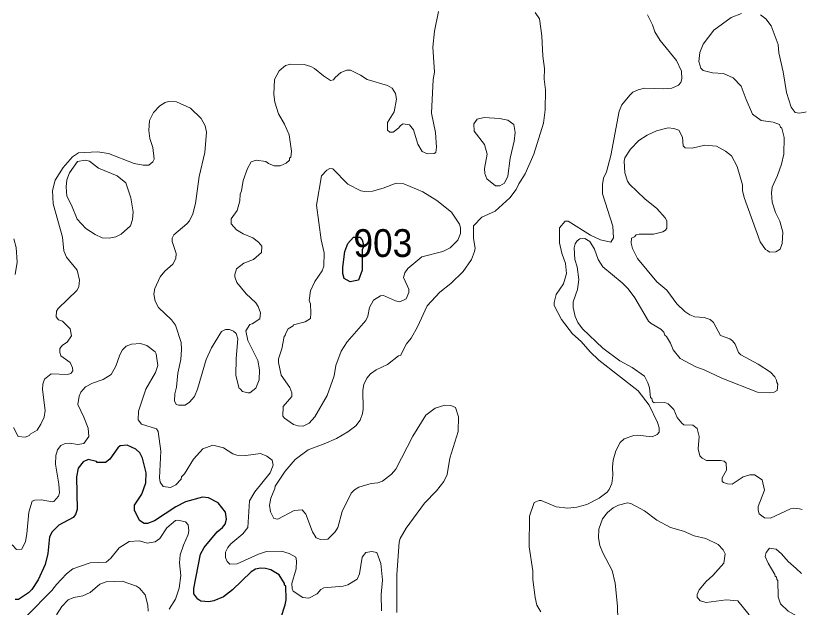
# Model space of a CAD drawing. Extents: x 598.3 to 623.2, y 6902.2 to 6930.1.
# Drawn here: x 620.795 to 623.07, y 6916.455 to 6918.158 of the extents above; entities that cross this region are included whole.
import ezdxf

# ---------------------------------------------------------------- set-up
doc = ezdxf.new("R2010")
doc.units = 0
doc.header["$LTSCALE"] = 0.032
doc.layers.add('1', color=7, linetype='Continuous', lineweight=25)
doc.layers.add('2', color=7, linetype='Continuous', lineweight=13)
doc.layers.add('21', color=7, linetype='Continuous')

msp = doc.modelspace()

# ---------------------------------------------------------------- linework, layer by layer
at = {"layer": '1'}
msp.add_lwpolyline([(621.7845, 6917.5203), (621.7917, 6917.5129), (621.7963, 6917.4943), (621.7917, 6917.4841), (621.7916, 6917.4254), (621.7808, 6917.3965), (621.7574, 6917.392), (621.7401, 6917.402), (621.7358, 6917.4158), (621.7358, 6917.4343), (621.7419, 6917.4795), (621.7504, 6917.5027), (621.7669, 6917.5205)], close=True, dxfattribs=at)
for points in [[(621.472, 6916.5568), (621.4187, 6916.5048), (621.3928, 6916.4854), (621.3645, 6916.4731), (621.3499, 6916.4707), (621.327, 6916.4721), (621.3188, 6916.4781), (621.3068, 6916.4937), (621.3075, 6916.5092), (621.3262, 6916.608), (621.3365, 6916.6267), (621.3742, 6916.6725), (621.3895, 6916.6847), (621.397, 6916.6944), (621.4014, 6916.7086), (621.3984, 6916.7292), (621.3769, 6916.7558), (621.3492, 6916.7697), (621.3318, 6916.7718), (621.2832, 6916.7588), (621.2555, 6916.7441), (621.1936, 6916.7036), (621.1739, 6916.6958), (621.1637, 6916.6958), (621.1503, 6916.7049), (621.136, 6916.7346), (621.136, 6916.7488), (621.1577, 6916.7806), (621.1684, 6916.813), (621.1698, 6916.8421), (621.1595, 6916.8845), (621.1515, 6916.8994), (621.1399, 6916.9102), (621.1156, 6916.9215), (621.0947, 6916.9193), (621.0883, 6916.9136), (621.0655, 6916.8812), (621.0523, 6916.8717), (621.0291, 6916.872), (621.0265, 6916.8747), (621.0025, 6916.8801), (620.9887, 6916.8738), (620.9741, 6916.855), (620.9692, 6916.8304), (620.9715, 6916.7362), (620.9668, 6916.7219), (620.96, 6916.713), (620.9185, 6916.691), (620.8994, 6916.672), (620.8914, 6916.6581), (620.8867, 6916.6102), (620.8794, 6916.5778), (620.8592, 6916.5341), (620.8406, 6916.5057), (620.8315, 6916.4965), (620.802, 6916.4777), (620.7931, 6916.4775)], [(621.5448, 6916.3851), (621.5701, 6916.4622), (621.573, 6916.4768), (621.5714, 6916.5165), (621.5683, 6916.5185), (621.568, 6916.5233), (621.553, 6916.548), (621.5289, 6916.5624), (621.5131, 6916.5669), (621.4986, 6916.5678), (621.4847, 6916.5647), (621.472, 6916.5568)]]:
    msp.add_lwpolyline(points, dxfattribs=at)
at = {"layer": '2'}
for points in [[(622.0111, 6918.17), (621.9996, 6918.1137), (621.9948, 6918.0679), (621.9997, 6917.9961), (621.9956, 6917.9747), (621.9908, 6917.8773), (622.0029, 6917.822), (622.0053, 6917.7794), (622.0038, 6917.7647), (621.9988, 6917.7611), (621.9795, 6917.7602), (621.9639, 6917.7677), (621.9515, 6917.788), (621.9394, 6917.8295), (621.9274, 6917.8443), (621.9096, 6917.8467), (621.9015, 6917.8425), (621.8968, 6917.8355), (621.8808, 6917.8229), (621.8714, 6917.8225), (621.8644, 6917.8284), (621.8644, 6917.8503), (621.8839, 6917.8811), (621.8903, 6917.9175), (621.8872, 6917.934), (621.8782, 6917.9494), (621.8647, 6917.9576), (621.8062, 6917.9747), (621.787, 6917.9875), (621.7576, 6918.0014), (621.7474, 6918.0013), (621.7305, 6917.9952), (621.7135, 6917.9807), (621.7091, 6917.9733), (621.7004, 6917.9716), (621.6802, 6917.9848), (621.6543, 6918.0061), (621.6434, 6918.0123), (621.6248, 6918.0176), (621.5861, 6918.0192), (621.5708, 6918.015), (621.5529, 6917.9992), (621.5391, 6917.9747), (621.5375, 6917.9317), (621.5406, 6917.9092), (621.5511, 6917.8759), (621.5676, 6917.8463), (621.581, 6917.8154), (621.5883, 6917.7681), (621.586, 6917.751), (621.5828, 6917.748), (621.5827, 6917.7426), (621.573, 6917.7335), (621.5552, 6917.7262), (621.5385, 6917.7263), (621.5215, 6917.7325), (621.5141, 6917.7385), (621.4867, 6917.7422), (621.4724, 6917.7372), (621.4611, 6917.7184), (621.4492, 6917.6836), (621.4443, 6917.6541), (621.4403, 6917.6444), (621.4394, 6917.625), (621.4321, 6917.5975)], [(622.0824, 6917.4213), (622.1063, 6917.4566), (622.1153, 6917.4791), (622.117, 6917.4893), (622.1122, 6917.5163), (622.1123, 6917.5535), (622.1365, 6917.578), (622.1749, 6917.5952), (622.2169, 6917.6336), (622.2352, 6917.6575), (622.2427, 6917.6742), (622.261, 6917.7025), (622.2856, 6917.7595), (622.3138, 6917.849), (622.3185, 6917.8868), (622.3194, 6917.9452), (622.3154, 6917.9758), (622.3161, 6918.006), (622.3113, 6918.0418), (622.3089, 6918.1008), (622.3017, 6918.149), (622.2896, 6918.1679)], [(622.6126, 6918.1607), (622.6277, 6918.132), (622.6342, 6918.1123), (622.6493, 6918.0869), (622.6968, 6918.0295), (622.7112, 6917.9984), (622.7113, 6917.9761), (622.7087, 6917.9658), (622.7024, 6917.9587), (622.6827, 6917.9494), (622.6597, 6917.9479), (622.6047, 6917.9497), (622.586, 6917.9453), (622.5708, 6917.9377), (622.5616, 6917.9295), (622.5394, 6917.9016), (622.5312, 6917.8831), (622.5071, 6917.7562), (622.4945, 6917.7084), (622.4863, 6917.6903), (622.483, 6917.6722), (622.4838, 6917.6458), (622.5127, 6917.5527), (622.5152, 6917.5184), (622.507, 6917.5061), (622.478, 6917.5132), (622.4484, 6917.5265), (622.3841, 6917.5667), (622.3758, 6917.5671), (622.3599, 6917.5473), (622.3597, 6917.5046), (622.3663, 6917.4744), (622.3769, 6917.4451), (622.3801, 6917.4161), (622.3711, 6917.3864), (622.3502, 6917.3551), (622.3445, 6917.3322), (622.3445, 6917.3234), (622.3657, 6917.2832), (622.397, 6917.2422), (622.4219, 6917.2204), (622.4479, 6917.1905), (622.4732, 6917.1667), (622.5859, 6917.0784), (622.6179, 6917.0373), (622.6414, 6916.9874), (622.6463, 6916.9715), (622.6464, 6916.9592), (622.6405, 6916.9522), (622.6262, 6916.9459), (622.5839, 6916.9506), (622.5731, 6916.9497), (622.5455, 6916.9401), (622.534, 6916.929), (622.5213, 6916.9054), (622.5137, 6916.8789), (622.512, 6916.8588), (622.5136, 6916.8344), (622.51, 6916.811), (622.5026, 6916.7942), (622.4965, 6916.7863), (622.4741, 6916.769), (622.4387, 6916.7506), (622.4098, 6916.7434), (622.3834, 6916.7403), (622.3499, 6916.7443), (622.3069, 6916.7628), (622.3011, 6916.7627), (622.2871, 6916.7564), (622.2734, 6916.7173), (622.2725, 6916.6288)], [(622.8834, 6918.1643), (622.8542, 6918.1534), (622.804, 6918.1167), (622.7728, 6918.0767), (622.7639, 6918.0527), (622.7606, 6918.0263), (622.7663, 6918.0072), (622.7729, 6918.0004), (622.8002, 6917.9938), (622.8316, 6917.9916), (622.8593, 6917.9795), (622.8827, 6917.9553), (622.8965, 6917.9167), (622.9151, 6917.8746), (622.9397, 6917.8565), (622.9746, 6917.8517), (622.9928, 6917.845), (622.9958, 6917.8369), (622.9995, 6917.8348), (623.0066, 6917.8079), (623.0051, 6917.76), (622.9986, 6917.7312), (622.9872, 6917.6981), (622.9719, 6917.6641), (622.9695, 6917.6485), (622.9719, 6917.6215), (622.981, 6917.5921), (622.9938, 6917.5665), (623.0025, 6917.5349), (623.0002, 6917.5022), (622.9944, 6917.4858), (622.9826, 6917.4783), (622.9637, 6917.4771), (622.9588, 6917.4824), (622.9521, 6917.4851), (622.9376, 6917.5071), (622.8908, 6917.6352), (622.8867, 6917.655), (622.8867, 6917.6709), (622.8707, 6917.7243), (622.8544, 6917.7545), (622.8372, 6917.7684), (622.8118, 6917.7827), (622.7775, 6917.7852), (622.7412, 6917.7764), (622.7217, 6917.7783), (622.716, 6917.7839), (622.7135, 6917.8085), (622.7033, 6917.8287), (622.6888, 6917.8338), (622.6721, 6917.8354), (622.6389, 6917.8264), (622.6121, 6917.8147), (622.5882, 6917.799), (622.5637, 6917.7743), (622.5479, 6917.7489), (622.5453, 6917.7391), (622.5477, 6917.7057), (622.555, 6917.6819), (622.5607, 6917.6728), (622.6057, 6917.6308), (622.64, 6917.603), (622.664, 6917.5766), (622.669, 6917.5681), (622.669, 6917.5467), (622.6646, 6917.5405), (622.6572, 6917.5357), (622.6299, 6917.529), (622.5893, 6917.5293), (622.5799, 6917.5269), (622.5752, 6917.5214), (622.5673, 6917.5174), (622.5663, 6917.5034), (622.5693, 6917.4883), (622.5842, 6917.4591), (622.6401, 6917.3924), (622.6681, 6917.3677), (622.6974, 6917.3287), (622.7207, 6917.3062), (622.735, 6917.2966), (622.7489, 6917.2914), (622.7759, 6917.289), (622.7934, 6917.2835), (622.8028, 6917.275), (622.823, 6917.2374), (622.85, 6917.2277)], [(623.0697, 6917.8815), (623.0666, 6917.8809), (623.0498, 6917.8776), (623.0378, 6917.8792), (623.0261, 6917.8951), (623.0132, 6917.9372), (623.0035, 6917.9971), (622.9912, 6918.0511), (622.9887, 6918.0757), (622.9684, 6918.1288), (622.9534, 6918.1493), (622.9381, 6918.1607)], [(621.4321, 6917.5975), (621.4144, 6917.573), (621.4148, 6917.5587), (621.4303, 6917.5418), (621.4487, 6917.5301), (621.4773, 6917.5189), (621.4935, 6917.5062), (621.5026, 6917.4943), (621.5018, 6917.4764), (621.4789, 6917.4565), (621.4506, 6917.4455), (621.4299, 6917.4292), (621.425, 6917.4134), (621.425, 6917.4062), (621.4307, 6917.39), (621.458, 6917.3572), (621.4856, 6917.3319), (621.4927, 6917.3207), (621.4985, 6917.3028), (621.4967, 6917.2857), (621.4753, 6917.2709), (621.4684, 6917.2693), (621.4566, 6917.2511), (621.4629, 6917.2235), (621.4912, 6917.1652), (621.4961, 6917.1383), (621.4947, 6917.11), (621.4858, 6917.0862), (621.4687, 6917.0726), (621.4627, 6917.0722), (621.4475, 6917.0766), (621.44, 6917.0842), (621.4372, 6917.0844), (621.4282, 6917.1222), (621.429, 6917.171), (621.4338, 6917.2283), (621.4288, 6917.2428), (621.4215, 6917.2503), (621.4095, 6917.255), (621.3978, 6917.255), (621.3869, 6917.2491), (621.3575, 6917.2019), (621.3427, 6917.1687), (621.3177, 6917.0832), (621.3089, 6917.0623), (621.2941, 6917.0458), (621.2822, 6917.0366), (621.2626, 6917.0366), (621.2559, 6917.039), (621.2518, 6917.0497), (621.2524, 6917.0695), (621.2573, 6917.0891), (621.2613, 6917.1294), (621.2694, 6917.1682), (621.2719, 6917.1971), (621.271, 6917.2176), (621.2538, 6917.2676), (621.2429, 6917.2823), (621.2049, 6917.3183), (621.1954, 6917.3359), (621.1918, 6917.3565), (621.1951, 6917.3727), (621.2103, 6917.4062), (621.2234, 6917.4227), (621.2465, 6917.4425), (621.2557, 6917.4593), (621.2564, 6917.4734), (621.2447, 6917.5086), (621.2445, 6917.5173), (621.2494, 6917.5272), (621.2868, 6917.559), (621.2941, 6917.5678), (621.3043, 6917.5877), (621.3116, 6917.6172), (621.3227, 6917.6953), (621.3383, 6917.7648), (621.3438, 6917.8231), (621.3395, 6917.841), (621.3281, 6917.8625), (621.2978, 6917.8921), (621.2571, 6917.91), (621.2344, 6917.9109), (621.2247, 6917.9082), (621.2093, 6917.8984), (621.1908, 6917.8796), (621.1797, 6917.8568), (621.1773, 6917.8281), (621.1804, 6917.8047), (621.1886, 6917.7786), (621.1926, 6917.7454), (621.1888, 6917.7379), (621.1775, 6917.7281), (621.1612, 6917.7277), (621.1357, 6917.7327), (621.0612, 6917.7619), (621.0301, 6917.7667), (620.9751, 6917.7632), (620.9579, 6917.7522), (620.9307, 6917.721), (620.9083, 6917.6847)], [(620.9083, 6917.6847), (620.9002, 6917.6548), (620.9019, 6917.6169), (620.9294, 6917.5203), (620.9327, 6917.4812), (620.9402, 6917.463), (620.9712, 6917.4256), (620.978, 6917.3967), (620.9764, 6917.3773), (620.9707, 6917.3668), (620.9164, 6917.3156), (620.9116, 6917.3075), (620.911, 6917.2914), (620.9171, 6917.283), (620.9289, 6917.2791), (620.951, 6917.2564), (620.9545, 6917.2368), (620.9423, 6917.2186), (620.9291, 6917.2093), (620.9216, 6917.2), (620.9214, 6917.1885), (620.9245, 6917.1792), (620.9513, 6917.1595), (620.9577, 6917.1439), (620.9586, 6917.1355), (620.9534, 6917.1282), (620.9432, 6917.1256), (620.8961, 6917.1272), (620.8769, 6917.1117), (620.872, 6917.097), (620.8712, 6917.0821), (620.8793, 6917.0211), (620.8761, 6917.002), (620.867, 6916.982), (620.8557, 6916.9651), (620.8363, 6916.953), (620.8341, 6916.9495), (620.8214, 6916.945), (620.8017, 6916.9469), (620.7883, 6916.9729)], [(620.7926, 6917.4129), (620.7984, 6917.4489), (620.7959, 6917.4909), (620.7885, 6917.5157)], [(622.85, 6917.2277), (622.8578, 6917.2224), (622.8648, 6917.2123), (622.8747, 6917.1889), (622.8819, 6917.1815), (622.9319, 6917.1548), (622.9671, 6917.1319), (622.9796, 6917.1186), (622.9847, 6917.1091), (622.9848, 6917.1023), (622.988, 6917.0972), (622.9863, 6917.0789), (622.9778, 6917.0744), (622.963, 6917.0722), (622.9295, 6917.0746), (622.8264, 6917.1149), (622.7762, 6917.1384), (622.7521, 6917.1471), (622.7069, 6917.1715), (622.6868, 6917.1964), (622.6787, 6917.2157), (622.6672, 6917.2348), (622.6627, 6917.2382), (622.6598, 6917.2466), (622.6509, 6917.2554), (622.6231, 6917.2718), (622.6159, 6917.2789), (622.5762, 6917.3463), (622.5575, 6917.3714), (622.5401, 6917.3888), (622.4847, 6917.4355), (622.4709, 6917.4564), (622.46, 6917.4863), (622.4472, 6917.5084), (622.4328, 6917.5172), (622.4183, 6917.5157), (622.4101, 6917.5101), (622.405, 6917.5014), (622.402, 6917.4898), (622.4042, 6917.456), (622.4101, 6917.4351), (622.415, 6917.3987), (622.4114, 6917.3699), (622.3987, 6917.3342), (622.3988, 6917.3185), (622.4045, 6917.2926), (622.4127, 6917.275), (622.4258, 6917.2563), (622.4848, 6917.2012), (622.5336, 6917.1649), (622.5685, 6917.1451), (622.6041, 6917.1201), (622.6142, 6917.1016), (622.6187, 6917.0865), (622.622, 6917.0585), (622.6253, 6917.0556), (622.6272, 6917.0478), (622.6321, 6917.0438), (622.6627, 6917.0447), (622.6723, 6917.0405), (622.6883, 6917.0247), (622.6983, 6917.0009), (622.7113, 6916.9847), (622.7179, 6916.9807), (622.7435, 6916.979), (622.7561, 6916.9698), (622.7621, 6916.9469), (622.7589, 6916.9114), (622.7632, 6916.8913), (622.7704, 6916.8843), (622.7824, 6916.8779), (622.8232, 6916.8778), (622.8338, 6916.8755), (622.839, 6916.8694), (622.8406, 6916.8498), (622.8278, 6916.8281), (622.8278, 6916.8174), (622.8312, 6916.8139), (622.8434, 6916.8099), (622.8564, 6916.8097), (622.8885, 6916.8305), (622.9071, 6916.8365), (622.9209, 6916.8364), (622.9426, 6916.8219), (622.9499, 6916.7921), (622.9315, 6916.7449), (622.9314, 6916.7346), (622.9347, 6916.7241), (622.9497, 6916.712), (622.9673, 6916.7111), (623.0242, 6916.7379), (623.0331, 6916.7401), (623.0504, 6916.7379), (623.0581, 6916.7369)], [(621.8911, 6916.4403), (621.8911, 6916.5496), (621.8977, 6916.6426), (621.9011, 6916.6526), (621.9187, 6916.6827), (621.9709, 6916.7545), (622.0053, 6916.7905), (622.027, 6916.8169), (622.0361, 6916.8375), (622.0435, 6916.8845), (622.0676, 6916.9612), (622.0684, 6917.0033), (622.0604, 6917.0305), (622.0469, 6917.0357), (622.0296, 6917.0373), (622.0018, 6917.0283), (621.9752, 6917.008), (621.9372, 6916.948), (621.8885, 6916.8525), (621.876, 6916.8383), (621.8501, 6916.8184), (621.8369, 6916.8131), (621.8173, 6916.8114), (621.7819, 6916.8009), (621.7691, 6916.7927), (621.7604, 6916.7836), (621.734, 6916.7311), (621.7214, 6916.6847), (621.7143, 6916.6726), (621.6923, 6916.651), (621.6721, 6916.6499), (621.6587, 6916.6547), (621.6489, 6916.6725), (621.6299, 6916.7226), (621.6186, 6916.7351), (621.5957, 6916.7337), (621.5488, 6916.7083), (621.5374, 6916.7104), (621.5277, 6916.73), (621.5253, 6916.7494), (621.5286, 6916.7688), (621.5404, 6916.7972), (621.5411, 6916.8039), (621.57, 6916.8473), (621.5989, 6916.8809), (621.636, 6916.9083), (621.6824, 6916.9251), (621.7177, 6916.9412), (621.7503, 6916.9599), (621.7738, 6916.9775), (621.7854, 6916.9941), (621.7923, 6917.0125), (621.7941, 6917.0249), (621.7939, 6917.0801), (621.7965, 6917.0961), (621.8047, 6917.1145), (621.8157, 6917.1269), (621.8316, 6917.139), (621.8644, 6917.154), (621.8965, 6917.1786), (621.9016, 6917.1799), (621.9192, 6917.2133), (621.9325, 6917.23), (621.9509, 6917.2621), (621.979, 6917.3227), (622.015, 6917.3619), (622.0466, 6917.387), (622.0824, 6917.4213)], [(621.8474, 6916.4445), (621.8466, 6916.4921), (621.8499, 6916.5327), (621.8449, 6916.5813), (621.8337, 6916.6122), (621.819, 6916.6156), (621.8017, 6916.6124), (621.7917, 6916.5988), (621.7835, 6916.5514), (621.7768, 6916.5354), (621.7501, 6916.5195), (621.7371, 6916.5153), (621.681, 6916.5111), (621.6729, 6916.5065), (621.6619, 6916.4933), (621.6382, 6916.4812), (621.6208, 6916.4826), (621.5925, 6916.5017), (621.59, 6916.5086), (621.5895, 6916.5234), (621.602, 6916.5656), (621.603, 6916.589), (621.6003, 6916.5988), (621.5814, 6916.6097), (621.5593, 6916.6163), (621.5158, 6916.6154), (621.4931, 6916.608), (621.4314, 6916.5801), (621.4109, 6916.5795), (621.4032, 6916.5871), (621.3982, 6916.5987), (621.3982, 6916.6135), (621.4053, 6916.6275), (621.414, 6916.6377), (621.4481, 6916.6663), (621.4627, 6916.6851), (621.4672, 6916.7612), (621.4824, 6916.787), (621.5265, 6916.8421), (621.5358, 6916.8643), (621.5325, 6916.8784), (621.5167, 6916.8898), (621.4993, 6916.898), (621.4567, 6916.8916), (621.4312, 6916.8927), (621.4192, 6916.8965), (621.392, 6916.9144), (621.362, 6916.9214), (621.3325, 6916.9112), (621.3058, 6916.8817), (621.28, 6916.839), (621.272, 6916.8301), (621.2703, 6916.8239), (621.2553, 6916.8079), (621.2395, 6916.8002), (621.2185, 6916.8027), (621.2105, 6916.8153), (621.208, 6916.8281), (621.212, 6916.9041), (621.204, 6916.9607), (621.1996, 6916.9686), (621.1567, 6916.9825), (621.1472, 6916.9943), (621.1481, 6917.0198), (621.1685, 6917.0832), (621.1966, 6917.1312), (621.2032, 6917.1508), (621.1982, 6917.1851), (621.1957, 6917.1902), (621.1718, 6917.2088), (621.1537, 6917.2145), (621.1278, 6917.2129), (621.1122, 6917.2063), (621.1018, 6917.1958), (621.0941, 6917.1822)], [(621.0941, 6917.1822), (621.0824, 6917.149), (621.0694, 6917.1248), (621.0459, 6917.1103), (621.0151, 6917.1), (620.9949, 6917.0897), (620.9822, 6917.0745), (620.9772, 6917.063), (620.9733, 6917.0389), (620.9907, 6917.0023), (621.0028, 6916.9703), (621.0052, 6916.9467), (620.99, 6916.9265), (620.973, 6916.924), (620.9492, 6916.9272), (620.9368, 6916.9264), (620.9239, 6916.9207), (620.9144, 6916.9079), (620.9102, 6916.8917), (620.9085, 6916.8667), (620.9189, 6916.8093), (620.9205, 6916.7846), (620.9174, 6916.7747), (620.9038, 6916.7598), (620.8998, 6916.7583), (620.8676, 6916.7646), (620.8491, 6916.7638), (620.8413, 6916.7603), (620.8317, 6916.7292), (620.8267, 6916.6668), (620.8226, 6916.6439), (620.8115, 6916.6223), (620.7965, 6916.6211), (620.7844, 6916.6345)], [(622.9054, 6916.4334), (622.8728, 6916.4731), (622.8389, 6916.4763), (622.7822, 6916.4691), (622.7641, 6916.4739), (622.7558, 6916.4839), (622.7558, 6916.4917), (622.7619, 6916.5047), (622.782, 6916.5293), (622.801, 6916.5468), (622.8326, 6916.5818), (622.8365, 6916.6085), (622.831, 6916.6202), (622.8164, 6916.6357), (622.7806, 6916.6529), (622.7472, 6916.6608), (622.7167, 6916.6742), (622.6788, 6916.6843), (622.6399, 6916.7062), (622.6043, 6916.7329), (622.5653, 6916.7541), (622.5557, 6916.7556), (622.5295, 6916.7493), (622.5144, 6916.741), (622.4977, 6916.7274), (622.4835, 6916.7095), (622.4732, 6916.6795), (622.4719, 6916.6547), (622.476, 6916.6324), (622.4843, 6916.6121), (622.5113, 6916.5608), (622.52, 6916.5247), (622.5266, 6916.4583), (622.5283, 6916.38)], [(620.826, 6916.4304), (620.8985, 6916.5036), (620.9113, 6916.5205), (620.9401, 6916.5509), (620.9592, 6916.5652), (621.0091, 6916.583), (621.0547, 6916.5849), (621.0683, 6916.5965), (621.0922, 6916.626), (621.1213, 6916.6447), (621.1505, 6916.6463), (621.1724, 6916.6399), (621.1962, 6916.6429), (621.2091, 6916.6532), (621.229, 6916.6835), (621.2542, 6916.705), (621.2612, 6916.7062), (621.2828, 6916.701), (621.2911, 6916.6925), (621.2929, 6916.6746), (621.291, 6916.6641), (621.2772, 6916.6338), (621.2678, 6916.6064), (621.2662, 6916.5827), (621.2694, 6916.5467), (621.2652, 6916.5102), (621.2547, 6916.4782)], [(622.2725, 6916.6288), (622.2829, 6916.5597), (622.2833, 6916.5349), (622.2893, 6916.483), (622.2948, 6916.4613), (622.3061, 6916.4415)], [(623.0562, 6916.5526), (623.0407, 6916.5663), (623.0177, 6916.5866), (622.9985, 6916.609), (622.9834, 6916.6222), (622.9639, 6916.6251), (622.9541, 6916.6131), (622.9517, 6916.6014), (622.9599, 6916.5818), (622.9796, 6916.5495), (622.9801, 6916.5443), (622.9844, 6916.5414), (622.9849, 6916.5346), (622.988, 6916.5319), (622.9889, 6916.485), (622.9962, 6916.4644), (623.0179, 6916.4441), (623.0334, 6916.4351), (623.0549, 6916.4226)], [(621.1755, 6916.4442), (621.1749, 6916.4611), (621.1668, 6916.4912), (621.1503, 6916.5097), (621.1419, 6916.5154), (621.1003, 6916.5297), (621.055, 6916.5281), (621.0369, 6916.5215), (621.009, 6916.4978), (620.9877, 6916.4874), (620.9618, 6916.4826), (620.9455, 6916.4761), (620.9271, 6916.4569), (620.9117, 6916.4335)], [(621.2547, 6916.4782), (621.2365, 6916.4497)]]:
    msp.add_lwpolyline(points, dxfattribs=at)
for points in [[(622.1431, 6917.8654), (622.1869, 6917.8621), (622.2107, 6917.8574), (622.2285, 6917.8453), (622.2319, 6917.822), (622.2288, 6917.7969), (622.2173, 6917.7478), (622.2109, 6917.6962), (622.2017, 6917.6757), (622.1882, 6917.668), (622.1754, 6917.668), (622.1503, 6917.6883), (622.1446, 6917.7041), (622.1437, 6917.7185), (622.1518, 6917.7594), (622.1441, 6917.787), (622.1138, 6917.8261), (622.113, 6917.8473), (622.1224, 6917.8607)], [(621.1245, 6917.5532), (621.1302, 6917.5716), (621.1327, 6917.5931), (621.1254, 6917.6334), (621.1116, 6917.6775), (621.0859, 6917.6969), (621.0328, 6917.7196), (621.0072, 6917.7395), (620.9938, 6917.7424), (620.9723, 6917.7381), (620.9496, 6917.7057), (620.9415, 6917.686), (620.9392, 6917.6651), (620.9419, 6917.6387), (620.9548, 6917.6131), (620.971, 6917.572), (620.9965, 6917.5458), (621.0226, 6917.528), (621.0436, 6917.519), (621.0634, 6917.5174), (621.0828, 6917.5214), (621.0974, 6917.5291)], [(621.7073, 6917.7171), (621.6982, 6917.7181), (621.6896, 6917.7132), (621.6749, 6917.6973), (621.6605, 6917.6127), (621.6733, 6917.5126), (621.6824, 6917.4758), (621.6815, 6917.4372), (621.6766, 6917.4235), (621.6557, 6917.3934), (621.6427, 6917.3662), (621.6394, 6917.3385), (621.6426, 6917.3286), (621.6442, 6917.3018), (621.6427, 6917.2863), (621.6279, 6917.2769), (621.5938, 6917.2682), (621.5932, 6917.2656), (621.5789, 6917.2565), (621.5707, 6917.2427), (621.5701, 6917.2373), (621.5666, 6917.2346), (621.5599, 6917.1987), (621.5512, 6917.1703), (621.5512, 6917.1598), (621.5584, 6917.1232), (621.5834, 6917.0877), (621.5892, 6917.0726), (621.5889, 6917.0621), (621.5643, 6917.0327), (621.5634, 6917.0053), (621.568, 6916.9995), (621.594, 6916.9812), (621.6073, 6916.9774), (621.6216, 6916.9767), (621.6394, 6916.9855), (621.6558, 6917.0034), (621.6912, 6917.0648), (621.7114, 6917.1215), (621.7156, 6917.1509), (621.7314, 6917.1922), (621.7485, 6917.2195), (621.802, 6917.2807), (621.8078, 6917.2934), (621.813, 6917.3183), (621.8246, 6917.339), (621.8442, 6917.3513), (621.8533, 6917.3531), (621.8871, 6917.3373), (621.8999, 6917.3344), (621.9184, 6917.343), (621.9259, 6917.3611), (621.9259, 6917.3708), (621.9108, 6917.4048), (621.9143, 6917.4177), (621.9233, 6917.4305), (621.963, 6917.4641), (622.0242, 6917.4792), (622.045, 6917.4901), (622.067, 6917.5117), (622.0749, 6917.5311), (622.0749, 6917.5473), (622.0716, 6917.5576), (622.0491, 6917.5924), (622.0061, 6917.6266), (621.9659, 6917.6516), (621.9112, 6917.6744), (621.8891, 6917.6761), (621.8525, 6917.6618), (621.8215, 6917.6531), (621.7993, 6917.6518), (621.7873, 6917.6537), (621.7506, 6917.6734)]]:
    msp.add_lwpolyline(points, close=True, dxfattribs=at)

# ---------------------------------------------------------------- texts
at = {"layer": '21', "width": 0.95}
msp.add_text('903', height=0.08, dxfattribs=at).set_placement((621.7664, 6917.4636))

doc.saveas('drawing.dxf')
